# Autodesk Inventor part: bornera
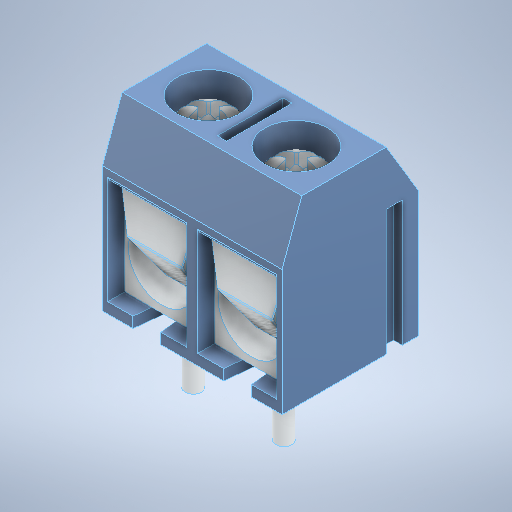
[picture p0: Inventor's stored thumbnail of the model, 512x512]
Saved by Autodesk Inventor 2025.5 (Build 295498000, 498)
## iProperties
Created: 2019-07
Part Number: bornera
Material: Genérico
Document SubType Name: Modeling
Designer: Luis M
Density: 1 g/cm^3
Appearance: Valor por defecto
Author: Luis M
Sending System: SolidWorks 2018
Last Author: User
Last Saved: 2019-07-13
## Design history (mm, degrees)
feature "Simetría4"
node "Plano1"
node "Plano2"
node "Plano8"
node "Plano9"
node "Plano11"
node "Plano12"
node "Plano13"
node "Sólido1"
